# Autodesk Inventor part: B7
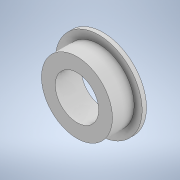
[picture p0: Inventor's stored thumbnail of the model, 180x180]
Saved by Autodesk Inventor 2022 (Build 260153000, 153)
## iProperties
Created: 2024-12
Part Number: B7
Material: 一般
Document SubType Name: Modeling
Designer: jsat7
Density: 1 g/cm^3
Appearance: 既定
Author: jsat7
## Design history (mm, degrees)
sketch "スケッチ1"
  geometry: C1 r 2.45 at (0, 0); 1 further point
  constraints: 1 centre point, 1 coincident
  dimensions: "d0" = 4.9 diameter of C1
extrude "押し出し1" new body sketch "スケッチ1" distance "d1" = 1.5; taper "d2" = 0 deg
sketch "スケッチ2"
  geometry: C1 r 3 at (0, 0); 1 further point
  constraints: 1 centre point, 1 coincident
  dimensions: "d3" = 6 diameter of C1
extrude "押し出し2" join sketch "スケッチ2" distance "d4" = 0.3; taper "d5" = 0 deg
sketch "スケッチ3"
  geometry: C1 r 1.5 at (0, 0); 1 further point
  constraints: 1 centre point, 1 coincident
  dimensions: "d6" = 3 diameter of C1
extrude "押し出し3" cut sketch "スケッチ3" distance "d7" = 1.8; taper "d8" = 0 deg
node "ソリッド1"
